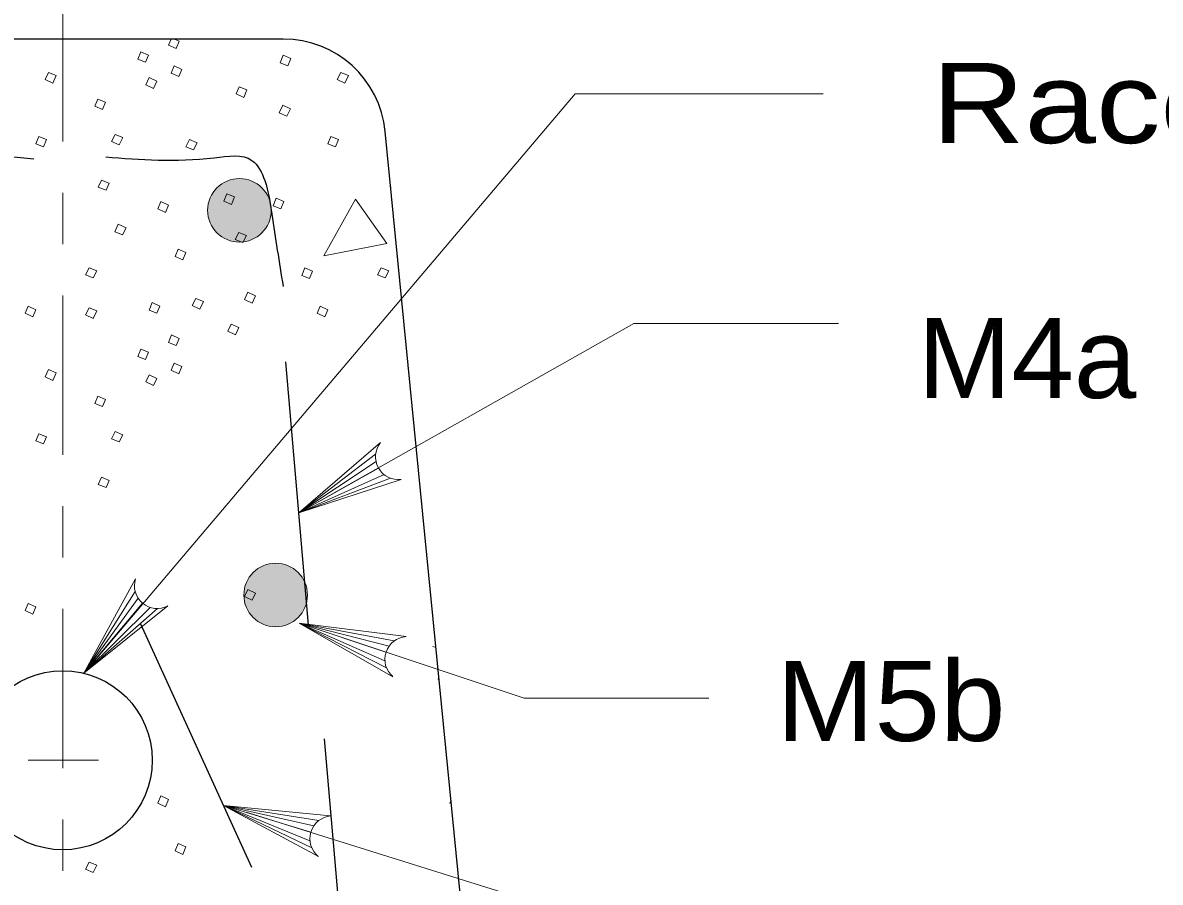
# Model space of a CAD drawing. Extents: x 1083.1 to 1123, y 697.4 to 741.4.
# Drawn here: x 1090.714 to 1092.929, y 715.405 to 717.078 of the extents above; entities that cross this region are included whole.
import ezdxf

# ---------------------------------------------------------------- set-up
doc = ezdxf.new("R2010")
doc.units = 0
doc.header["$LTSCALE"] = 0.062
doc.linetypes.add('DOT_DASHED', pattern=[7.7, 5, -1.2, 0.3, -1.2])
doc.layers.add('1', color=7, linetype='Continuous', lineweight=13)

msp = doc.modelspace()

# ---------------------------------------------------------------- hatches: boundary and pattern name
at = {"layer": '1'}
h = msp.add_hatch(color=256, dxfattribs=at)
edge = h.paths.add_edge_path()
edge.add_ellipse((1091.13569, 716.71311), major_axis=(0.06191, 0), ratio=0.9998948, start_angle=0, end_angle=360)
h = msp.add_hatch(color=256, dxfattribs=at)
edge = h.paths.add_edge_path()
edge.add_ellipse((1091.20623, 715.96415), major_axis=(0.06191, 0), ratio=0.9998948, start_angle=0, end_angle=360)

# ---------------------------------------------------------------- linework, layer by layer
at = {"layer": '1', "linetype": 'DOT_DASHED'}
msp.add_line((1090.7915, 717.157), (1090.7915, 713.82992), dxfattribs=at)
at = {"layer": '1', "lineweight": 25}
for p, q in [((1091.22108, 717.04658), (1090.38058, 717.04658)), ((1091.27008, 715.90542), (1091.22617, 716.41808)), ((1090.943, 715.90783), (1091.15942, 715.43417)), ((1091.37642, 714.81975), (1091.30158, 715.68408))]:
    msp.add_line(p, q, dxfattribs=at)
at = {"layer": '1'}
for p, q in [((1091.25133, 716.12392), (1091.90375, 716.49292)), ((1091.90375, 716.49292), (1092.3025, 716.49292)), ((1091.40083, 716.23817), (1091.25133, 716.12392)), ((1091.40167, 716.22383), (1091.25133, 716.12392)), ((1091.40642, 716.21142), (1091.25133, 716.12392)), ((1091.4175, 716.1985), (1091.25133, 716.12392)), ((1091.42967, 716.19142), (1091.25133, 716.12392)), ((1090.93242, 715.97125), (1090.83283, 715.81167)), ((1090.93825, 715.95808), (1090.83283, 715.81167)), ((1090.94717, 715.94825), (1090.83283, 715.81167)), ((1090.962, 715.93992), (1090.83283, 715.81167)), ((1090.97592, 715.93767), (1090.83283, 715.81167)), ((1091.421, 715.853), (1091.25225, 715.90942)), ((1091.419, 715.836), (1091.25225, 715.90942)), ((1091.42183, 715.82233), (1091.25225, 715.90942)), ((1091.42708, 715.86475), (1091.25225, 715.90942)), ((1091.43717, 715.875), (1091.25225, 715.90942)), ((1091.51242, 715.86417), (1091.51858, 715.86167)), ((1090.86092, 715.64233), (1090.72392, 715.64233)), ((1091.27475, 715.50267), (1091.10442, 715.55458)), ((1091.273, 715.48575), (1091.10442, 715.55458)), ((1091.27633, 715.472), (1091.10442, 715.55458)), ((1091.28042, 715.51467), (1091.10442, 715.55458)), ((1091.29017, 715.52525), (1091.10442, 715.55458))]:
    msp.add_line(p, q, dxfattribs=at)
for points in [[(1091.0095, 717.04658), (1091.0185, 717.04242), (1091.0125, 717.02842), (1090.99758, 717.03442), (1091.00242, 717.04658)], [(1090.83542, 715.81475), (1091.78967, 716.93992), (1092.2725, 716.93992)], [(1091.43042, 716.75775), (1091.42958, 716.75808), (1091.43025, 716.75958)], [(1091.45075, 716.18925), (1091.25133, 716.12392), (1091.41025, 716.26092)], [(1090.99642, 715.94308), (1090.83283, 715.81167), (1090.93342, 715.99583)], [(1091.25225, 715.90942), (1091.68983, 715.7635), (1092.04967, 715.7635)], [(1091.43433, 715.80508), (1091.25225, 715.90942), (1091.46042, 715.88325)], [(1091.52467, 715.79917), (1091.52242, 715.80025), (1091.52417, 715.8045)], [(1091.54842, 715.55733), (1091.54533, 715.55883), (1091.54775, 715.5645)], [(1091.28933, 715.45517), (1091.10442, 715.55458), (1091.31325, 715.53392)], [(1091.14858, 715.54108), (1091.8065, 715.33567), (1092.11775, 715.33567)]]:
    msp.add_lwpolyline(points, dxfattribs=at)
for points in [[(1090.94367, 717.02142), (1090.95867, 717.01542), (1090.95267, 717.0015), (1090.93767, 717.0075)], [(1091.22108, 717.01542), (1091.236, 717.0085), (1091.23, 716.9945), (1091.21508, 717.0005)], [(1090.76408, 716.9815), (1090.779, 716.97558), (1090.77208, 716.96058), (1090.75708, 716.96758)], [(1091.0085, 716.9945), (1091.0235, 716.9875), (1091.0175, 716.97358), (1091.0025, 716.9805)], [(1091.33283, 716.9815), (1091.34775, 716.97558), (1091.34075, 716.96058), (1091.32583, 716.96758)], [(1090.95967, 716.97158), (1090.97458, 716.96458), (1090.96858, 716.95058), (1090.95367, 716.95758)], [(1091.13525, 716.95358), (1091.15017, 716.94758), (1091.14425, 716.93267), (1091.12925, 716.93967)], [(1090.85983, 716.92967), (1090.87483, 716.92367), (1090.86883, 716.90967), (1090.85383, 716.91567)], [(1091.22008, 716.91767), (1091.235, 716.91067), (1091.228, 716.89675), (1091.21308, 716.90275)], [(1090.74508, 716.85683), (1090.76008, 716.85083), (1090.75408, 716.83683), (1090.73908, 716.84283)], [(1090.89375, 716.86083), (1090.90875, 716.85483), (1090.90175, 716.84083), (1090.88683, 716.84683)], [(1091.03842, 716.85083), (1091.05342, 716.84483), (1091.04642, 716.83092), (1091.0315, 716.83683)], [(1091.31383, 716.85683), (1091.32883, 716.85083), (1091.32283, 716.83683), (1091.30783, 716.84283)], [(1090.86683, 716.772), (1090.88183, 716.766), (1090.87583, 716.75208), (1090.86083, 716.75808)], [(1091.11133, 716.74508), (1091.12625, 716.73908), (1091.12025, 716.72417), (1091.10533, 716.73108)], [(1091.20708, 716.73708), (1091.22208, 716.73008), (1091.21608, 716.71617), (1091.20108, 716.72217)], [(1091.36175, 716.73508), (1091.29983, 716.62433), (1091.42258, 716.64833)], [(1090.98258, 716.73008), (1090.99758, 716.72317), (1090.99158, 716.70917), (1090.97658, 716.71617)], [(1090.89975, 716.68625), (1090.91475, 716.67925), (1090.90775, 716.66525), (1090.89275, 716.67125)], [(1091.13425, 716.67025), (1091.14917, 716.66425), (1091.14225, 716.65033), (1091.12725, 716.65625)], [(1091.0165, 716.63733), (1091.0315, 716.63133), (1091.0255, 716.61642), (1091.0105, 716.62333)], [(1090.84292, 716.60142), (1090.85783, 716.59542), (1090.85083, 716.5815), (1090.83592, 716.58742)], [(1091.26292, 716.60142), (1091.27792, 716.59442), (1091.27192, 716.5805), (1091.257, 716.58642)], [(1091.41158, 716.60142), (1091.42658, 716.59542), (1091.41958, 716.5815), (1091.40467, 716.58742)], [(1091.05042, 716.54158), (1091.06542, 716.53558), (1091.05842, 716.52058), (1091.04342, 716.52758)], [(1091.15217, 716.5535), (1091.16717, 716.54658), (1091.16017, 716.53258), (1091.14525, 716.53958)], [(1090.72417, 716.52658), (1090.73908, 716.51958), (1090.73317, 716.50567), (1090.71817, 716.51267)], [(1090.84292, 716.52358), (1090.85783, 716.51758), (1090.85083, 716.50267), (1090.83592, 716.50958)], [(1090.96558, 716.53358), (1090.98058, 716.52658), (1090.97458, 716.51267), (1090.95967, 716.51858)], [(1091.29292, 716.52658), (1091.30783, 716.51958), (1091.30183, 716.50567), (1091.28692, 716.51267)], [(1091.11925, 716.49167), (1091.13425, 716.48467), (1091.12825, 716.47075), (1091.11325, 716.47767)], [(1091.0035, 716.47075), (1091.0185, 716.46375), (1091.0125, 716.44975), (1090.99758, 716.45575)], [(1090.94367, 716.44275), (1090.95867, 716.43683), (1090.95267, 716.42283), (1090.93767, 716.42883)], [(1090.76408, 716.40292), (1090.779, 716.39692), (1090.77208, 716.38192), (1090.75708, 716.38892)], [(1091.0085, 716.41583), (1091.0235, 716.40883), (1091.0175, 716.39492), (1091.0025, 716.40192)], [(1090.95967, 716.39292), (1090.97458, 716.38592), (1090.96858, 716.37192), (1090.95367, 716.37892)], [(1090.85983, 716.351), (1090.87483, 716.345), (1090.86883, 716.331), (1090.85383, 716.337)], [(1090.74508, 716.27817), (1090.76008, 716.27217), (1090.75408, 716.25825), (1090.73908, 716.26417)], [(1090.89375, 716.28217), (1090.90875, 716.27617), (1090.90175, 716.26217), (1090.88683, 716.26817)], [(1090.86683, 716.19333), (1090.88183, 716.18733), (1090.87583, 716.17342), (1090.86083, 716.17942)], [(1091.15217, 715.97492), (1091.16717, 715.96792), (1091.16017, 715.95392), (1091.14525, 715.96092)], [(1090.72417, 715.94792), (1090.73908, 715.94092), (1090.73317, 715.927), (1090.71817, 715.934)], [(1090.98258, 715.57283), (1090.99758, 715.56583), (1090.99158, 715.55183), (1090.97658, 715.55883)], [(1091.0165, 715.48), (1091.0315, 715.47408), (1091.0255, 715.45908), (1091.0105, 715.46608)], [(1090.84292, 715.44408), (1090.85783, 715.43817), (1090.85083, 715.42417), (1090.83592, 715.43017)]]:
    msp.add_lwpolyline(points, close=True, dxfattribs=at)
at = {"layer": '1', "lineweight": 25}
msp.add_lwpolyline([(1092.86625, 713.35117), (1092.28325, 713.35117), (1092.28325, 713.89792), (1091.6065, 714.96742), (1091.41967, 716.86658)], dxfattribs=at)
msp.add_ellipse((1091.22108, 716.84704), major_axis=(0.19956, 0), ratio=0.999895, start_param=0.09795, end_param=1.5707963, dxfattribs=at)
at = {"layer": '1'}
for centre in [(1091.13569, 716.71311), (1091.20623, 715.96415)]:
    msp.add_ellipse(centre, major_axis=(0.06191, 0), ratio=0.999895, dxfattribs=at)
for centre, major_axis, start_param, end_param in [((1091.44507, 716.23328), (-0.04422, 0.00419), 5.7065563, 8.0771694), ((1090.97562, 715.98225), (-0.04442, 0), 5.9717573, 8.3423705), ((1091.46321, 715.83888), (0.03742, 0.02392), 1.0648754, 3.4354885), ((1091.31723, 715.4897), (-0.04442, 0), 4.8020462, 7.1726593)]:
    msp.add_ellipse(centre, major_axis=major_axis, ratio=0.999895, start_param=start_param, end_param=end_param, dxfattribs=at)
at = {"layer": '1', "lineweight": 25}
msp.add_ellipse((1090.7915, 715.64235), major_axis=(0.17433, 0), ratio=0.999895, dxfattribs=at)
for points in [[(1090.383, 716.51242), (1090.39558, 716.67233), (1090.41242, 716.751), (1090.45775, 716.79867), (1090.52658, 716.81783), (1090.73533, 716.81358)], [(1090.87542, 716.81725), (1091.08658, 716.8155), (1091.16008, 716.81025), (1091.18483, 716.7715), (1091.19883, 716.70567), (1091.22075, 716.56508)]]:
    msp.add_spline(points, degree=3, dxfattribs=at)

# ---------------------------------------------------------------- texts
at = {"layer": '1'}
for s, width, p in [('Raceway', 1.2, (1092.48392, 716.84408)), ('M4a', 1.05, (1092.4565, 716.34767)), ('M5b', 1.1, (1092.18117, 715.67992))]:
    msp.add_text(s, height=0.156, dxfattribs=dict(at, width=width)).set_placement(p)

doc.saveas('drawing.dxf')
